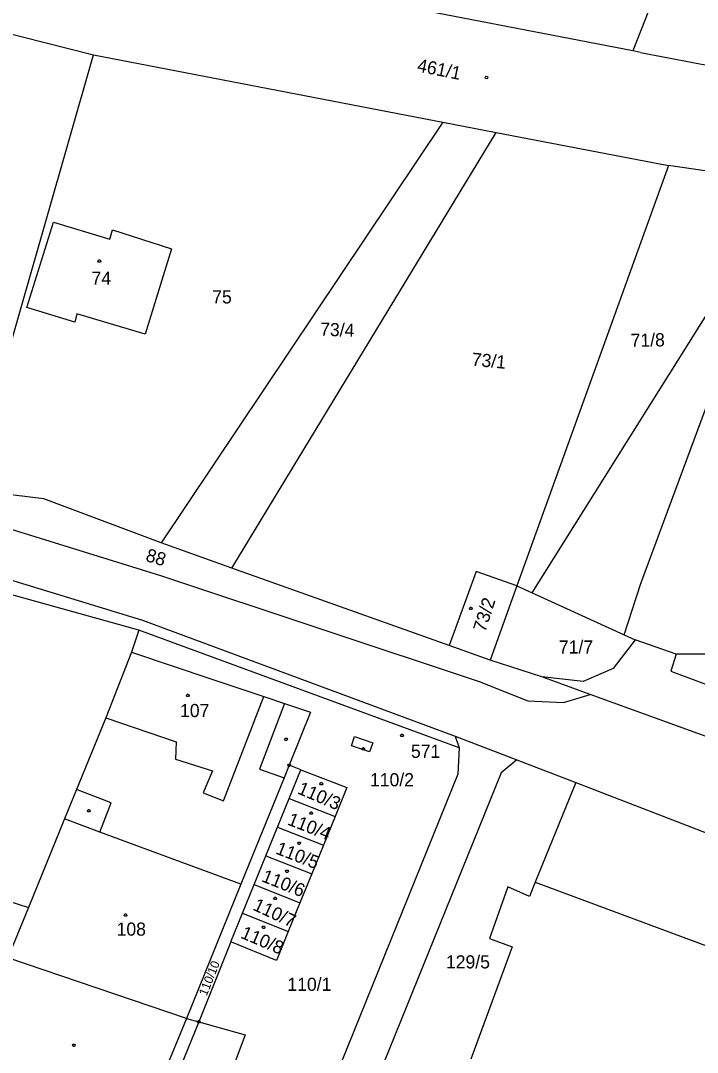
# Model space of a CAD drawing. Extents: x -634640 to -629202, y -1196156 to -1190068.
# Drawn here: x -631277.6 to -631190.1, y -1192756.2 to -1192622.8 of the extents above; entities that cross this region are included whole.
import ezdxf

# ---------------------------------------------------------------- set-up
doc = ezdxf.new("R2010")
doc.units = 0
for name, color, linetype in [('Vrstva 1', 7, 'Continuous'), ('Vrstva 2', 7, 'Continuous'), ('Vrstva 3', 7, 'Continuous'), ('Vrstva 4', 7, 'Continuous'), ('Vrstva 5', 7, 'Continuous'), ('Vrstva 7', 7, 'Continuous'), ('Vrstva 8', 7, 'Continuous')]:
    doc.layers.add(name, color=color, linetype=linetype)

msp = doc.modelspace()

# ---------------------------------------------------------------- linework, layer by layer
at = {"layer": 'Vrstva 1'}
for p, q in [((-631198.41, -1192626.69), (-631355.77, -1192596.21)), ((-631295.87, -1192620.24), (-631268.16, -1192627.17)), ((-631196.36, -1192621.41), (-631198.41, -1192626.69)), ((-631197.45, -1192626.88), (-631198.41, -1192626.69)), ((-631197.45, -1192626.88), (-631165.89, -1192632.99)), ((-631284.27, -1192683.42), (-631268.16, -1192627.17)), ((-631268.16, -1192627.17), (-631222.97, -1192635.9)), ((-631222.97, -1192635.9), (-631259.4, -1192690.32)), ((-631222.97, -1192635.9), (-631216.09, -1192637.23)), ((-631250.28, -1192693.57), (-631216.09, -1192637.23)), ((-631216.09, -1192637.23), (-631193.81, -1192641.52)), ((-631193.81, -1192641.52), (-631213.41, -1192695.89)), ((-631178.26, -1192643.8), (-631193.81, -1192641.52)), ((-631211.42, -1192696.79), (-631178.26, -1192643.8)), ((-631276.76, -1192659.86), (-631273.34, -1192648.84)), ((-631273.34, -1192648.84), (-631266.06, -1192651.02)), ((-631266.06, -1192651.02), (-631265.7, -1192649.82)), ((-631265.7, -1192649.82), (-631258.05, -1192652.28)), ((-631197.37, -1192695.57), (-631180.87, -1192650.9)), ((-631258.05, -1192652.28), (-631261.49, -1192663.3)), ((-631270.59, -1192661.75), (-631276.76, -1192659.86)), ((-631270.29, -1192660.67), (-631270.59, -1192661.75)), ((-631261.49, -1192663.3), (-631270.29, -1192660.67)), ((-631259.47, -1192694.58), (-631311.89, -1192678.27)), ((-631313.75, -1192684.44), (-631261.8, -1192700.32)), ((-631274.56, -1192684.62), (-631284.27, -1192683.42)), ((-631259.4, -1192690.32), (-631274.56, -1192684.62)), ((-631250.28, -1192693.57), (-631259.4, -1192690.32)), ((-631262.31, -1192701.6), (-631290.96, -1192693.63)), ((-631222.15, -1192703.59), (-631250.28, -1192693.57)), ((-631217.84, -1192708.42), (-631259.47, -1192694.58)), ((-631218.7, -1192694.01), (-631222.15, -1192703.59)), ((-631213.41, -1192695.89), (-631218.7, -1192694.01)), ((-631213.41, -1192695.89), (-631216.86, -1192705.48)), ((-631213.41, -1192695.89), (-631211.42, -1192696.79)), ((-631199.55, -1192702.2), (-631197.37, -1192695.57)), ((-631211.42, -1192696.79), (-631199.55, -1192702.2)), ((-631261.8, -1192700.32), (-631221.4, -1192715.3)), ((-631262.31, -1192701.6), (-631263.26, -1192704.47)), ((-631220.86, -1192716.82), (-631262.31, -1192701.6)), ((-631198.1, -1192702.86), (-631200.98, -1192706.56)), ((-631199.55, -1192702.2), (-631198.1, -1192702.86)), ((-631192.82, -1192704.69), (-631198.1, -1192702.86)), ((-631263.26, -1192704.47), (-631266.58, -1192712.93)), ((-631263.26, -1192704.47), (-631252.85, -1192707.95)), ((-631216.86, -1192705.48), (-631222.15, -1192703.59)), ((-631210.19, -1192707.65), (-631216.86, -1192705.48)), ((-631192.82, -1192704.69), (-631193.51, -1192706.91)), ((-631188.24, -1192704.69), (-631192.82, -1192704.69)), ((-631200.98, -1192706.56), (-631204.84, -1192708.24)), ((-631193.51, -1192706.91), (-631159.94, -1192719.41)), ((-631252.85, -1192707.95), (-631246.12, -1192710.2)), ((-631217.84, -1192708.42), (-631212.01, -1192710.74)), ((-631203.94, -1192709.92), (-631210.19, -1192707.65)), ((-631204.84, -1192708.24), (-631210.19, -1192707.65)), ((-631246.12, -1192710.2), (-631243.44, -1192711.09)), ((-631243.44, -1192711.09), (-631240.1, -1192712.21)), ((-631212.01, -1192710.74), (-631207.38, -1192710.97)), ((-631207.38, -1192710.97), (-631203.94, -1192709.92)), ((-631163.2, -1192724.72), (-631203.94, -1192709.92)), ((-631240.1, -1192712.21), (-631242.85, -1192719.08)), ((-631266.58, -1192712.93), (-631270.35, -1192722.21)), ((-631234.8, -1192716.56), (-631234.4, -1192715.38)), ((-631234.4, -1192715.38), (-631232.06, -1192716.16)), ((-631232.06, -1192716.16), (-631232.45, -1192717.35)), ((-631221.4, -1192715.3), (-631220.86, -1192716.82)), ((-631221.4, -1192715.3), (-631215.11, -1192717.73)), ((-631232.45, -1192717.35), (-631234.8, -1192716.56)), ((-631220.86, -1192716.82), (-631221.05, -1192720.23)), ((-631215.11, -1192717.73), (-631213.43, -1192718.38)), ((-631242.85, -1192719.08), (-631243.49, -1192720.69)), ((-631241.34, -1192719.65), (-631242.85, -1192719.08)), ((-631213.43, -1192718.38), (-631215.45, -1192720.07)), ((-631213.43, -1192718.38), (-631205.78, -1192721.33)), ((-631221.05, -1192720.23), (-631243.22, -1192775.11)), ((-631242.85, -1192723.36), (-631241.34, -1192719.65)), ((-631241.34, -1192719.65), (-631235.39, -1192721.96)), ((-631215.45, -1192720.07), (-631231.76, -1192760.36)), ((-631243.49, -1192720.69), (-631249.09, -1192734.48)), ((-631205.78, -1192721.33), (-631211.03, -1192734.22)), ((-631205.78, -1192721.33), (-631179.34, -1192731.54)), ((-631270.35, -1192722.21), (-631271.9, -1192726)), ((-631235.39, -1192721.96), (-631236.91, -1192725.69)), ((-631244.36, -1192727.08), (-631242.85, -1192723.36)), ((-631242.85, -1192723.36), (-631236.91, -1192725.69)), ((-631236.91, -1192725.69), (-631238.42, -1192729.41)), ((-631271.9, -1192726), (-631276.58, -1192737.47)), ((-631267.35, -1192727.73), (-631271.9, -1192726)), ((-631245.87, -1192730.79), (-631244.36, -1192727.08)), ((-631244.36, -1192727.08), (-631238.42, -1192729.41)), ((-631249.09, -1192734.48), (-631267.35, -1192727.73)), ((-631301.4, -1192729.6), (-631276.58, -1192737.47)), ((-631238.42, -1192729.41), (-631239.94, -1192733.14)), ((-631247.37, -1192734.5), (-631245.87, -1192730.79)), ((-631245.87, -1192730.79), (-631239.94, -1192733.14)), ((-631239.94, -1192733.14), (-631241.46, -1192736.87)), ((-631249.09, -1192734.48), (-631256.12, -1192751.82)), ((-631248.88, -1192738.22), (-631247.37, -1192734.5)), ((-631247.37, -1192734.5), (-631241.46, -1192736.87)), ((-631214.57, -1192734.82), (-631216.94, -1192741.47)), ((-631211.78, -1192736.06), (-631214.57, -1192734.82)), ((-631211.03, -1192734.22), (-631211.78, -1192736.06)), ((-631211.03, -1192734.22), (-631183.04, -1192744.61)), ((-631276.58, -1192737.47), (-631279.24, -1192744)), ((-631241.46, -1192736.87), (-631242.97, -1192740.6)), ((-631250.39, -1192741.93), (-631248.88, -1192738.22)), ((-631248.88, -1192738.22), (-631242.97, -1192740.6)), ((-631242.97, -1192740.6), (-631244.49, -1192744.33)), ((-631216.94, -1192741.47), (-631214.04, -1192742.55)), ((-631250.39, -1192741.93), (-631254.55, -1192752.26)), ((-631244.49, -1192744.33), (-631250.39, -1192741.93)), ((-631214.04, -1192742.55), (-631219.35, -1192757.09)), ((-631256.12, -1192751.82), (-631279.24, -1192744)), ((-631256.12, -1192751.82), (-631263.39, -1192769.4)), ((-631254.55, -1192752.26), (-631261.74, -1192769.87)), ((-631256.12, -1192751.82), (-631254.55, -1192752.26)), ((-631254.55, -1192752.26), (-631248.54, -1192753.93)), ((-631248.54, -1192753.93), (-631255.23, -1192771.71))]:
    msp.add_line(p, q, dxfattribs=at)
at = {"layer": 'Vrstva 3'}
for points in [[(-631217.222, -1192629.991), (-631217.163, -1192630.155), (-631217.281, -1192630.285), (-631217.458, -1192630.249), (-631217.517, -1192630.085), (-631217.399, -1192629.955), (-631217.222, -1192629.991)], [(-631263.93, -1192738.3), (-631263.84, -1192738.45), (-631263.93, -1192738.6), (-631264.11, -1192738.6), (-631264.2, -1192738.45), (-631264.11, -1192738.3), (-631263.93, -1192738.3)], [(-631270.6, -1192755.15), (-631270.51, -1192755.3), (-631270.6, -1192755.45), (-631270.78, -1192755.45), (-631270.87, -1192755.3), (-631270.78, -1192755.15), (-631270.6, -1192755.15)]]:
    msp.add_lwpolyline(points, dxfattribs=at)
at = {"layer": 'Vrstva 4'}
for p, q in [((-631251.34, -1192723.66), (-631246.12, -1192710.2)), ((-631243.44, -1192711.09), (-631246.68, -1192719.59)), ((-631266.58, -1192712.93), (-631257.45, -1192716.05)), ((-631257.45, -1192716.05), (-631257.57, -1192718.29)), ((-631257.57, -1192718.29), (-631252.78, -1192719.8)), ((-631252.78, -1192719.8), (-631253.96, -1192722.66)), ((-631246.68, -1192719.59), (-631243.49, -1192720.69)), ((-631265.87, -1192723.94), (-631270.35, -1192722.21)), ((-631253.96, -1192722.66), (-631251.34, -1192723.66)), ((-631267.35, -1192727.73), (-631265.87, -1192723.94))]:
    msp.add_line(p, q, dxfattribs=at)
at = {"layer": 'Vrstva 5'}
for points in [[(-631267.31, -1192653.72), (-631267.22, -1192653.87), (-631267.31, -1192654.02), (-631267.49, -1192654.02), (-631267.58, -1192653.87), (-631267.49, -1192653.72), (-631267.31, -1192653.72)], [(-631219.27, -1192698.64), (-631219.18, -1192698.79), (-631219.27, -1192698.94), (-631219.45, -1192698.94), (-631219.54, -1192698.79), (-631219.45, -1192698.64), (-631219.27, -1192698.64)], [(-631255.86, -1192709.89), (-631255.77, -1192710.04), (-631255.86, -1192710.19), (-631256.04, -1192710.19), (-631256.13, -1192710.04), (-631256.04, -1192709.89), (-631255.86, -1192709.89)], [(-631243.17, -1192715.57), (-631243.08, -1192715.72), (-631243.17, -1192715.87), (-631243.35, -1192715.87), (-631243.44, -1192715.72), (-631243.35, -1192715.57), (-631243.17, -1192715.57)], [(-631238.61, -1192721.31), (-631238.52, -1192721.46), (-631238.61, -1192721.61), (-631238.79, -1192721.61), (-631238.88, -1192721.46), (-631238.79, -1192721.31), (-631238.61, -1192721.31)], [(-631268.67, -1192724.81), (-631268.58, -1192724.96), (-631268.67, -1192725.11), (-631268.85, -1192725.11), (-631268.94, -1192724.96), (-631268.85, -1192724.81), (-631268.67, -1192724.81)], [(-631239.92, -1192725.11), (-631239.83, -1192725.26), (-631239.92, -1192725.41), (-631240.1, -1192725.41), (-631240.19, -1192725.26), (-631240.1, -1192725.11), (-631239.92, -1192725.11)], [(-631241.46, -1192729.01), (-631241.37, -1192729.16), (-631241.46, -1192729.31), (-631241.64, -1192729.31), (-631241.73, -1192729.16), (-631241.64, -1192729.01), (-631241.46, -1192729.01)], [(-631243.05, -1192732.64), (-631242.96, -1192732.79), (-631243.05, -1192732.94), (-631243.23, -1192732.94), (-631243.32, -1192732.79), (-631243.23, -1192732.64), (-631243.05, -1192732.64)], [(-631244.59, -1192736.15), (-631244.5, -1192736.3), (-631244.59, -1192736.45), (-631244.77, -1192736.45), (-631244.86, -1192736.3), (-631244.77, -1192736.15), (-631244.59, -1192736.15)], [(-631246.07, -1192739.89), (-631245.98, -1192740.04), (-631246.07, -1192740.19), (-631246.25, -1192740.19), (-631246.34, -1192740.04), (-631246.25, -1192739.89), (-631246.07, -1192739.89)]]:
    msp.add_lwpolyline(points, dxfattribs=at)
at = {"layer": 'Vrstva 7'}
msp.add_line((-631233.33, -1192716.84), (-631233.27, -1192716.97), dxfattribs=at)
msp.add_lwpolyline([(-631233.295, -1192717.143), (-631233.436, -1192717.04), (-631233.411, -1192716.867), (-631233.245, -1192716.797), (-631233.104, -1192716.9), (-631233.129, -1192717.073), (-631233.295, -1192717.143)], dxfattribs=at)
at = {"layer": 'Vrstva 8'}
for points in [[(-631228.18, -1192715.06), (-631228.09, -1192715.21), (-631228.18, -1192715.36), (-631228.36, -1192715.36), (-631228.45, -1192715.21), (-631228.36, -1192715.06), (-631228.18, -1192715.06)], [(-631242.76, -1192718.93), (-631242.67, -1192719.08), (-631242.76, -1192719.23), (-631242.94, -1192719.23), (-631243.03, -1192719.08), (-631242.94, -1192718.93), (-631242.76, -1192718.93)], [(-631254.46, -1192752.11), (-631254.37, -1192752.26), (-631254.46, -1192752.41), (-631254.64, -1192752.41), (-631254.73, -1192752.26), (-631254.64, -1192752.11), (-631254.46, -1192752.11)]]:
    msp.add_lwpolyline(points, dxfattribs=at)

# ---------------------------------------------------------------- texts
at = {"layer": 'Vrstva 2'}
for s, height, rotation, p in [('461/1', 1.7, 348.53023, (-631226.407, -1192629.317)), ('73/4', 1.7, 357.86944, (-631238.873, -1192663.509)), ('71/8', 1.7, 1.14592, (-631198.693, -1192664.975)), ('73/1', 1.7, 354.66087, (-631219.304, -1192667.392)), ('88', 1.7, 343.02983, (-631261.523, -1192692.619)), ('73/2', 1.7, 72.36457, (-631217.498, -1192701.954)), ('110/3', 1.7, 336.89918, (-631241.899, -1192722.694)), ('110/4', 1.7, 338.56076, (-631243.194, -1192726.724)), ('110/5', 1.7, 338.78994, (-631244.714, -1192730.482)), ('110/6', 1.7, 338.33158, (-631246.535, -1192734.065)), ('110/7', 1.7, 335.12301, (-631247.664, -1192737.735)), ('110/8', 1.7, 336.89918, (-631249.249, -1192741.364)), ('110/10', 1.14, 68.23927, (-631253.525, -1192748.997))]:
    msp.add_text(s, height=height, rotation=rotation, dxfattribs=at).set_placement(p)
for s, height, p in [('74', 1.7, (-631268.403, -1192656.92)), ('75', 1.7, (-631252.803, -1192659.35)), ('71/7', 1.7, (-631207.983, -1192704.63)), ('107', 1.7, (-631256.967, -1192712.85)), ('110/2', 0.1, (-631233.307, -1192716.84)), ('108', 1.7, (-631265.167, -1192741.12)), ('129/5', 1.7, (-631222.587, -1192745.36)), ('110/1', 1.7, (-631243.087, -1192748.26))]:
    msp.add_text(s, height=height, dxfattribs=at).set_placement(p)
at = {"layer": 'Vrstva 7'}
msp.add_text('110/2', height=1.7, dxfattribs=at).set_placement((-631232.407, -1192721.8))
at = {"layer": 'Vrstva 8'}
msp.add_text('571', height=1.7, dxfattribs=at).set_placement((-631227.113, -1192718.12))

doc.saveas('drawing.dxf')
